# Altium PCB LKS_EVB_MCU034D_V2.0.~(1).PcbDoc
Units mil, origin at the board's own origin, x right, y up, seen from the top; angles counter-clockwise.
Board outline 2625 x 1560 mil, 2 copper layers (Top Layer, Bottom Layer); 35 components, 49 nets, 172 pads, 81 vias.
Unrouted connection lines stored in the file: 35.
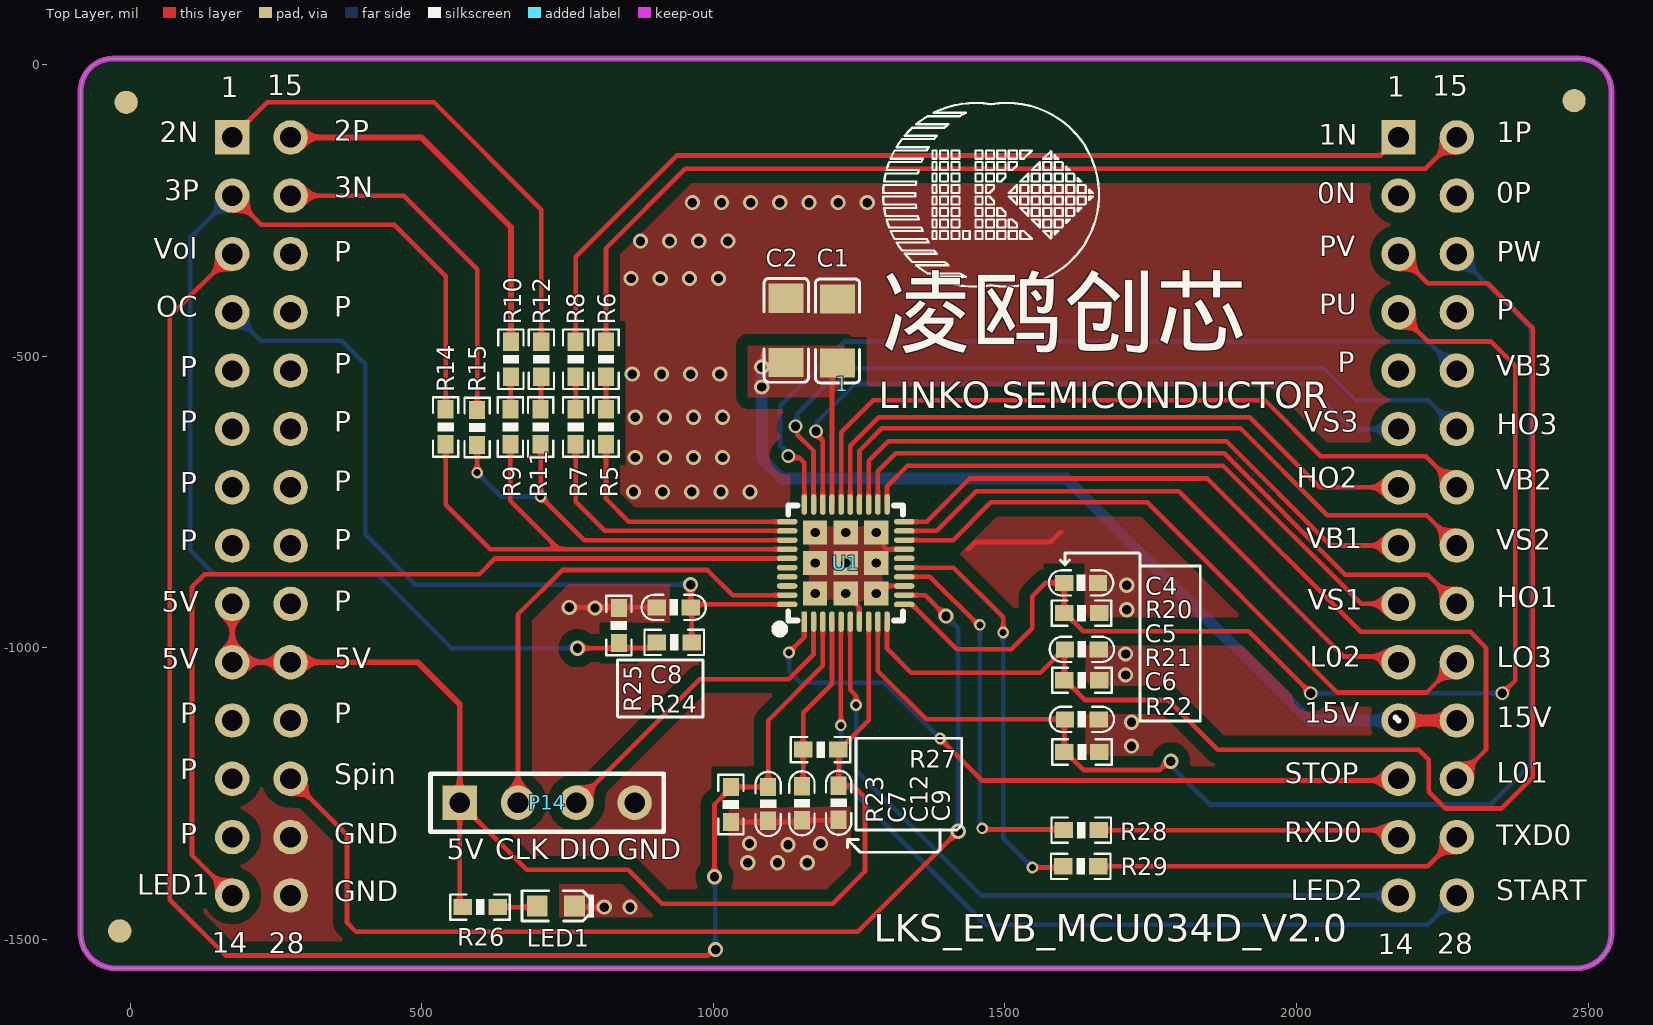
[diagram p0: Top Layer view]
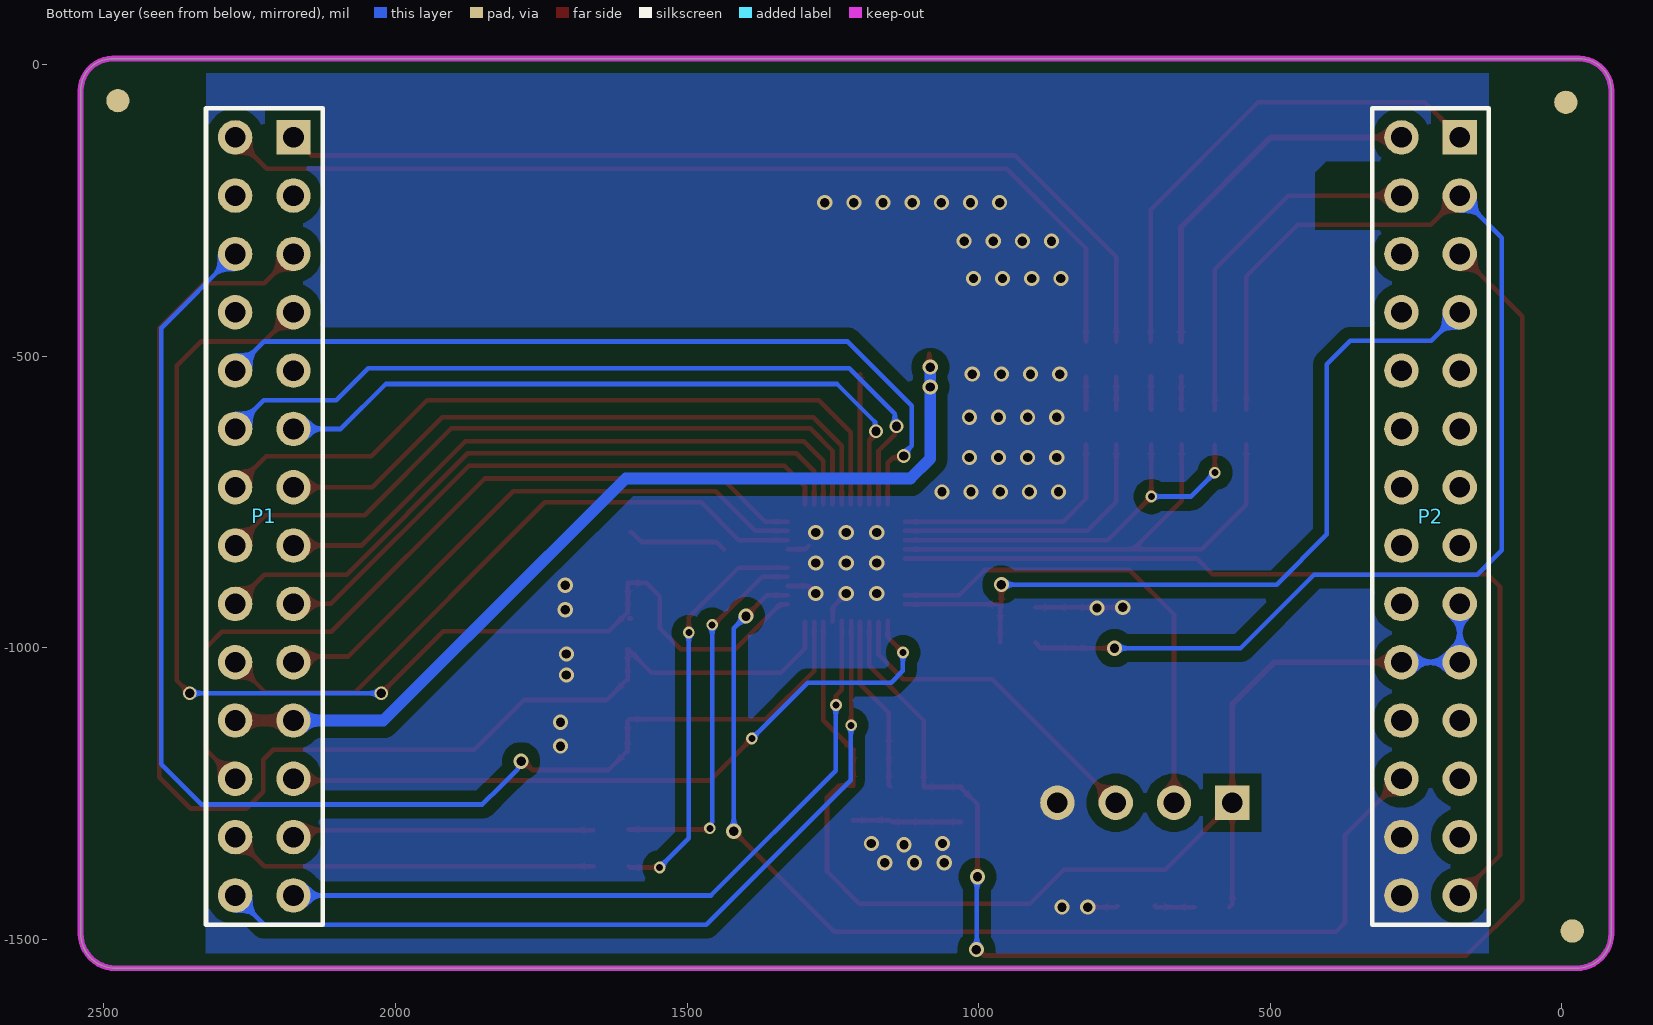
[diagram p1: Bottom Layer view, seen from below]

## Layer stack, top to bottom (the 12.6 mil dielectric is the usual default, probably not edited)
Top Solder: solder mask 0.4, Solder Resist, Dk 3.5
Top Layer: signal copper 1.4
Dielectric1: dielectric 12.6, FR-4, Dk 4.8
Bottom Layer: signal copper 1.4
Bottom Solder: solder mask 0.4, Solder Resist, Dk 3.5

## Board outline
-85,-1490 ccw(c-25,-1490) -25,-1550 2480,-1550 ccw(c2480,-1490) 2540,-1490 2540,-45 ccw(c2485,-45) 2485,10 -30,10 ccw(c-30,-45) -85,-45

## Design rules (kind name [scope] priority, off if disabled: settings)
Clearance Clearance_1 [InPolygon] p1: gap=20 ignorepadtopadclearanceinfootprint=FALSE except(0: Arc-Hole Track-Hole SMDPad-Hole THPad-Hole Via-Hole Fill-Hole Poly-Hole Region-Hole Text-Hole)
Clearance [All] p2: gap=5 ignorepadtopadclearanceinfootprint=FALSE
ComponentClearance [All] p1: gap=0 collisioncheckmode=3 verticalgap=0 showdistances=FALSE
FabricationTestpoint [(IsPad And (OnTopLayer Or OnBottomLayer))] p1: side=3 testpointundercomponent=TRUE minsize=40 maxsize=100 preferedsize=60 minholesize=0 maxholesize=40 preferedholesize=32 testpointgrid=1 allowsidetop=TRUE allowsidebottom=TRUE usegrid=TRUE gridtolerance=0.01
HoleSize [All] p1: absolutevalues=TRUE maxlimit=100 minlimit=0 maxpercent=80.000 minpercent=20.000
PolygonConnect [All] p1: connectstyle=Direct reliefconductorwidth=30 reliefentries=4 polygonreliefangle="90 Angle" airgapwidth=10
RoutingVias [All] p1: holewidth=12 width=20 viastyle="Through Hole" minholewidth=0 minwidth=10 maxholewidth=100 maxwidth=200
SilkToSolderMaskClearance SilkscreenOverComponentPads [IsPad] p1: minsilkscreentomaskgap=10 clearancetoexposedcopper=TRUE
SolderMaskExpansion [All] p1: expansion=4 istentingtop=FALSE
Width [All] p1: maxlimit=100 minlimit=2 preferedwidth=10
26 further rules are at their usual default settings.

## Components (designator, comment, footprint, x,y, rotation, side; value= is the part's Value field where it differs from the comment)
1 "LKS_sign" LKS_LOGO2 1221,-548 r0 top
C1 "22uF/25V" 1206C 1213,-457 r90 top
C2 "22uF/25V" 1206C 1125,-456 r90 top
C4 "1nF/16V" 0603C 1630.52,-889.02 r0 top
C5 "1nF/16V" 0603C 1632,-1003 r0 top
C6 "1nF/16V" 0603C 1632,-1123 r0 top
C7 "100nF/50V" 0603C 1094,-1268 r90 top
C8 "1nF/50V" 0603C 932,-931 r0 top
C9 "1uF/16V" 0603C 1215,-1266 r90 top
C12 "100nF/50V" 0603C 1152,-1267 r270 top
LED1 "LED" 0603D 730,-1443 r0 top
P1 "Header 14X2A" "HDR2 2X14 底层" 2175,-125 r270 bottom
P2 "Header 14X2A" "HDR2 2X14 底层" 175,-125 r270 bottom
P14 "Header 4" "HDR 1X4" 565,-1266 r0 top
R5 "20K" 0603R 815.95,-621.56 r270 top value=K
R6 "20K" 0603R 815.95,-505.56 r270 top value=K
R7 "20K" 0603R 763.95,-621.56 r270 top value=K
R8 "20K" 0603R 763.95,-505.56 r270 top value=K
R9 "20K" 0603R 651.95,-621.56 r270 top value=K
R10 "20K" 0603R 652.95,-505.56 r270 top value=K
R11 "20K" 0603R 703.95,-621.56 r270 top value=K
R12 "20K" 0603R 704.95,-505.56 r270 top value=K
R14 "1K" 0603R 540.95,-621.56 r270 top value=K
R15 "1K" 0603R 594.95,-622.56 r270 top value=K
R20 "1K" 0603R 1631.52,-941.02 r0 top value=K
R21 "1K" 0603R 1632.01,-1056 r0 top value=K
R22 "1K" 0603R 1632.05,-1179.01 r0 top value=K
R23 "1K" 0603R 1030,-1269 r90 top value=K
R24 "1K" 0603R 933,-991 r180 top value=K
R25 "10R" 0603R 838,-962 r90 top value=K
R26 "3.3K" 0603R 600,-1445 r180 top value=330
R27 "20K" 0603R 1184,-1175 r180 top value=K
R28 "10R" 0603R 1631,-1313 r180 top value=K
R29 "10R" 0603R 1630,-1375 r180 top value=K
U1 "LKS034DO" LINKO-084D 1156.13,-955.39 r90 top

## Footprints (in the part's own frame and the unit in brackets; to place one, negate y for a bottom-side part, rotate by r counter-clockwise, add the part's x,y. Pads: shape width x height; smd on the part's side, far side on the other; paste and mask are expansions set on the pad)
0603C [mm] "电容"
  rect 0.8x0.7 smd: 1(-0.737,0) 2(0.738,0)
  silkscreen extent -1.4,-0.55 1.4,0.55, body extent -0.8,-0.41 0.8,0.41, height 0.81
0603D [mm]
  rect 0.9x0.9 smd: 1(-0.813,0) 2(0.813,0)
  silkscreen extent -1.47,-0.66 1.65,0.66
0603R [mm] "电阻"
  rect 0.8x0.7 smd: 1(-0.762,0) 2(0.762,0)
  silkscreen extent -1.3,-0.55 1.3,0.55, body extent -0.8,-0.4 0.8,0.4, height 0.45
1206C [mil]
  rect 50x60 smd: 1(-55,0) 2(55,0)
  silkscreen extent -89,-38 89,38, body extent -61,-31 65,32, height 24
"HDR2 2X14 底层" [mm] "排针-双 2.54mm 底层"
  rect 1.5x1.5 hole 0.9: 1(0,0)
  round 1.5 hole 0.9: 2(2.54,0) 3(5.08,0) 4(7.62,0) 5(10.16,0) 6(12.7,0) 7(15.24,0) 8(17.78,0) 9(20.32,0) 10(22.86,0) 11(25.4,0) 12(27.94,0) 13(30.48,0) 14(33.02,0) 15(0,-2.54) 16(2.54,-2.54) 17(5.08,-2.54) 18(7.62,-2.54) 19(10.16,-2.54) 20(12.7,-2.54) 21(15.24,-2.54) 22(17.78,-2.54) 23(20.32,-2.54) 24(22.86,-2.54) 25(25.4,-2.54) 26(27.94,-2.54) 27(30.48,-2.54) 28(33.02,-2.54)
  silkscreen extent -1.27,-3.81 34.29,1.27, body extent -1.27,-6.35 34.29,-1.27, height 8.5
"HDR 1X4" [mm] "排针-单 2.54mm"
  rect 1.5x1.5 hole 0.9: 1(0,0)
  round 1.5 hole 0.9: 2(2.54,0) 3(5.08,0) 4(7.62,0)
  silkscreen extent -1.27,-1.27 8.89,1.27, body extent -1.27,-1.27 8.89,1.27, height 8.5
LINKO-084D [mm]
  rect 1.05x1.05 smd: 0(1.22,-3.13) 0(1.22,-0.47) 0(1.22,-1.8) 0(2.55,-1.8) 0(2.55,-0.47) 0(2.55,-3.13) 0(3.88,-3.13) 0(3.88,-1.8) 0(3.88,-0.47)
  rect 0.9x0.24 smd: 1(0,0)
  oval 0.9x0.24 smd: 2(0,-0.4) 3(0,-0.8) 4(0,-1.2) 5(0,-1.6) 6(0,-2) 7(0,-2.4) 8(0,-2.8) 9(0,-3.2) 10(0,-3.6) 21(5.1,-3.6) 22(5.1,-3.2) 23(5.1,-2.8) 24(5.1,-2.4) 25(5.1,-2) 26(5.1,-1.6) 27(5.1,-1.2) 28(5.1,-0.8) 29(5.1,-0.4) 30(5.1,0)
  oval 0.24x0.9 smd: 11(0.75,-4.35) 12(1.15,-4.35) 13(1.55,-4.35) 14(1.95,-4.35) 15(2.35,-4.35) 16(2.75,-4.35) 17(3.15,-4.35) 18(3.55,-4.35) 19(3.95,-4.35) 20(4.35,-4.35) 31(4.35,0.75) 32(3.95,0.75) 33(3.55,0.75) 34(3.15,0.75) 35(2.75,0.75) 36(2.35,0.75) 37(1.95,0.75) 38(1.55,0.75) 39(1.15,0.75) 40(0.75,0.75)
  silkscreen extent -0.44,-4.3 5.05,1.19
LKS_LOGO2 [mil] "标?"
  silkscreen extent 70,167 440,482

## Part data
C1 C2: library part Capacitor, "Capacitor --贴片电容"
C4 C5 C6: library part CAP, "Capacitor"
C7 C8 C9 C12: library part C, "Capacitor"
LED1: "LED_Light"
P1 P2: "Header, 14-Pin, Dual row"
P14: "Header, 4-Pin"
R5 R6 R7 R8 R9 R10 R11 R12 R14 R15 R20 R21 R22 R23 R24 R25 R26 R27 R28 R29: library part Res, "Resistor"
U1: library part LKS32MC034DF6Q8, "CHIP"

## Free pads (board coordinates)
  round 40 all layers, no hole: 5(-18,-1486) 5(-7,-65) 5(2476,-62)

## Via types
v1: diameter 26, hole 16, Top Layer to Bottom Layer, 66 vias
v2: diameter 20, hole 12, Top Layer to Bottom Layer, 10 vias
v3: diameter 23.62, hole 15.75, Top Layer to Bottom Layer, 5 vias

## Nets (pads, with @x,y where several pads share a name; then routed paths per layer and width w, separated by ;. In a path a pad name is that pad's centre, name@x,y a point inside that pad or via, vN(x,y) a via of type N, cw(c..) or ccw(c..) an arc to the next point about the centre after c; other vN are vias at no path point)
+5V: C9.2 P2.9 P2.10 P2.24 P14.1 R26.2 R27.1 U1.8 | length 2345.3
  Top Layer w8: R26.2 565,-1440 P14.1 680,-1381 854,-1381 912,-1439 1205,-1439 1260,-1384 1260,-1256.99 1239.96,-1236.95 C9.2 ; C9.2@1215,-1234.95 1215,-1176 R27.1 1215.97,-1175 1266.37,-1124.6 U1.8
  Top Layer w10: P2.9 P2.10 P2.24 493,-1025 565,-1097 P14.1
  Bottom Layer w8: P14.1 P14.1@567,-1268
  Bottom Layer w10: P2.9 P2.10 P2.24
+15V: C1.1 C2.1 P1.11 P1.25 U1.27 | length 1782
  Top Layer w8: v1(1083,-519) 1084.68,-517.32 1084.68,-495.97 ; U1.27 C1.1@1203.38,-531
  Top Layer w20: P1.11 P1.25
  Bottom Layer w20: v1(1083,-519) v1(1083,-553) 1083,-676 1117,-710 1605,-710 1737,-842 ; 1737.5,-841.5 2021,-1125 P1.11
GND: C1.2 C2.2 C4.2 C5.2 C6.2 C7.1 C8.1 C9.1 C12.2 LED1.2 P2.27 P2.28 P14.4 R20.2 R21.2 R22.2 R23.1 R25.2 U1.0 U1.7 U1.13 U1.17 | length 712.8
  Top Layer w8: v1(753,-931) C8.1 ; LED1.2 764,-1445 v1(813,-1445) ; R23.1 1149.05,-1299 C12.2 1213.95,-1296.05 C9.1 C9.1@1215,-1296.97 ; v1(1227,-907.36) 1250.34,-930.71 1250.34,-955.12 U1.7 ; v1(1279.36,-907.36) 1292.35,-894.37 U1.13 ; 1291.11,-825.28 1297.21,-831.38 U1.17 ; 1436.76,-831.38 1449.14,-819 1577.98,-819 1594.98,-802 1596.94,-802
  other v1: 857,-1445 1059,-1369 1110,-1369 1161,-1369 1128,-1338 1062,-1336 1184,-1336 1717,-1169 1717,-1128 1707,-1047 1707,-1011 1709,-935 797,-932 1174.64,-907.36 1709,-893 1174.64,-855 1227,-855 1279.36,-855 1174.64,-802.64 1227,-802.64 1279.36,-802.64 863,-733 913,-733 963,-733 1013,-733 1063,-733 866,-674 916,-674 966,-674 1016,-674 866,-605 916,-605 966,-605 1016,-605 861,-531 911,-531 961,-531 1011,-531 859,-367 909,-367 959,-367 1009,-367 875,-303 925,-303 975,-303 1025,-303 964,-237 1014,-237 1064,-237 1114,-237 1164,-237 1214,-237 1264,-237
GND0: P2.16 R15.1 | length 613.7
  Top Layer w8: P2.16 469,-225 594.95,-350.95 R15.1
HO1: P1.23 U1.22 | length 1169.3
  Top Layer w8: U1.22 1282.12,-697.88 1313,-667 1876,-667 2084,-875 2225,-875 P1.23
HO2: P1.7 U1.25 | length 1110.7
  Top Layer w8: U1.25 1234.87,-654.13 1284,-605 1920,-605 2040,-725 P1.7
HO3: P1.20 U1.29 | length 1376
  Top Layer w8: v3(1141,-620.47) 1143.99,-623.46 1143.99,-634.99 1171.88,-662.88 U1.29
  Bottom Layer w8: v3(1141,-620.47) 1143.99,-617.49 1143.99,-599.01 1222,-521 2047,-521 2102,-576 2226,-576 P1.20
LED1: P2.14 U1.35 | length 1598.4
  Top Layer w8: P2.14 106,-1356 106,-896 128,-874 599,-874 625.87,-847.13 U1.35
LED2: P1.14 U1.6 | length 1278.4
  Top Layer w8: U1.6@1234.51,-953.76 1234.51,-1072.24 1244.64,-1082.36 v2(1244.64,-1098.36)
  Bottom Layer w8: v2@1245,-1100 1245,-1211 1459,-1425 P1.14
LO1: P1.26 U1.20 | length 1394.1
  Top Layer w8: U1.20 1365.87,-784.13 1440,-710 1847,-710 2110,-973 2298,-973 2325,-1000 2325,-1175 P1.26
LO2: P1.10 U1.19 | length 997.1
  Top Layer w8: U1.19 1383.12,-799.88 1451,-732 1798,-732 2081.23,-1015.23 2165.23,-1015.23 P1.10
LO3: P1.24 U1.18 | length 1130.9
  Top Layer w8: U1.18 1411.37,-815.63 1476,-751 1744,-751 2070,-1077 2223,-1077 P1.24
NetLED1_1: LED1.1 R26.1 | length 70.2
  Top Layer w8: R26.1 696,-1445 LED1.1 LED1.1@697,-1442
NetR5_1: R5.1 R6.2 | length 56
  Top Layer w8: R5.1 R6.2
NetR7_1: R7.1 R8.2 | length 56
  Top Layer w8: R7.1 R8.2
NetR9_1: R9.1 R10.2 | length 56.4
  Top Layer w8: R9.1@652.45,-591.06 R10.2@652.45,-536.06
  Top Layer w9.45: R9.1 R9.1@652.45,-591.06 ; R10.2@652.45,-536.06 R10.2
NetR11_1: R11.1 R12.2 | length 56.4
  Top Layer w8: R11.1@704.45,-591.06 R12.2@704.45,-536.06
  Top Layer w9.45: R11.1 R11.1@704.45,-591.06 ; R12.2@704.45,-536.06 R12.2
NetR28_2: R28.2 U1.14 | length 655.3
  Top Layer w8: U1.14 1327.53,-878.48 1371.4,-878.48 1453.92,-961 v2(1457,-961) ; v2(1461,-1310) 1463,-1312 R28.2@1601,-1312
  Bottom Layer w8: v2(1457,-961) 1457,-1299.31 1458.7,-1301.02 1458.7,-1307.7 v2(1461,-1310)
NetR29_2: R29.2 U1.15 | length 708.4
  Top Layer w8: U1.15 1411.87,-862.87 1497,-948 v2(1497,-974) ; v2(1547,-1377) 1598,-1377 R29.2
  Bottom Layer w8: v2(1497,-974) 1497,-1327 v2(1547,-1377)
NRST: C12.1 R27.2 U1.4 | length 303.9
  Top Layer w8: C12.1 1154,-1236 R27.2 1154,-1112 1203.38,-1062.62 U1.4
OC: C8.2 P2.4 R24.1 U1.40 | length 1414.4
  Top Layer w8: v1(961,-892) 961.05,-892.05 C8.2 963,-932.95 R24.1 ; C8.2@962.52,-925.87 U1.40
  Bottom Layer w8: P2.4 224,-474 363,-474 403,-514 403,-806 489,-892 v1(961,-892)
OPA0_IN: R7.2 U1.32 | length 481.7
  Top Layer w8: R7.2 763.95,-749.95 813.88,-799.88 U1.32
OPA0_IP: R5.2 U1.31 | length 420.3
  Top Layer w8: R5.2 815.95,-744.95 855.13,-784.13 U1.31
OPA1_IN: R11.2 R15.2 U1.33 | length 716.4
  Top Layer w8: R15.2 v2(594.95,-699.95) v2@595,-700 ; R11.2 v2(703.95,-740.95) 778.63,-815.63 U1.33
  Bottom Layer w8: v2(594.95,-699.95) 635.95,-740.95 v2(703.95,-740.95)
OPA1_IP: R9.2 R14.2 U1.34 | length 934.9
  Top Layer w8: R14.2 540.95,-754.95 617.38,-831.38 735,-831.38 ; R9.2 651.95,-748.32 735,-831.38 ; U1.34 851.38,-831.38 735,-831.38
PGND: P2.2 R14.1 R24.2 R25.1 | length 2163.2
  Top Layer w8: P2.2 225,-275 453,-275 540.95,-362.95 R14.1 ; v1(767,-1001) 833.17,-1001 833.39,-1000.78 893.22,-1000.78 R24.2
  Bottom Layer w8: P2.2 103,-297 103,-833 145,-875 425,-875 551,-1001 v1(767,-1001)
PGND0: P1.2
PGND1: P1.1 R8.1 | length 1641.5
  Top Layer w8: R8.1 763.95,-330.05 938,-156 2144,-156 P1.1
PGND2: P2.1 R12.1 | length 857.6
  Top Layer w8: P2.1 235,-65 521,-65 704.95,-248.95 R12.1
PU: C4.1 P1.4 R20.1 U1.11 | length 2059
  Top Layer w8: U1.11 1340.39,-925.87 1417.52,-1003 1511,-1003 1547,-967 1547,-912 1569.98,-889.02 C4.1 R20.1 1603.49,-941.02 1634.47,-972 1918,-972 v3(2024.4,-1078.4) ; R20.1@1595.54,-950 R20.1@1600,-950 ; P1.4 2225,-475 2333,-475 2375,-517 2375,-1056.4 v3(2353,-1078.4)
  Bottom Layer w8: v3(2024.4,-1078.4) v3(2353,-1078.4)
PV: C5.1 P1.3 R21.1 U1.10 | length 2439.9
  Top Layer w8: U1.10 1297.87,-1001.87 1339,-1043 1561.03,-1043 1601.03,-1003 C5.1 1602.01,-1003.99 R21.1 1603.98,-1056 1637.97,-1090 1780,-1090 1865,-1175 2210,-1175 2227,-1192 2227,-1247 2256,-1276 2351,-1276 2405,-1222 2405,-452 2328,-375 2225,-375 P1.3
PW: C6.1 P1.17 R22.1 U1.9 | length 2303.2
  Top Layer w8: U1.9 1282.12,-1040.12 1365,-1123 1598.54,-1123 1602.05,-1126.52 R22.1 1604.02,-1179.01 1635.01,-1210 1764.69,-1210 1779.69,-1195 v1(1784.56,-1195)
  Bottom Layer w8: v1(1784.56,-1195) 1784.56,-1199.87 1790.46,-1205.77 1790.46,-1208.46 1819.5,-1237.5 1851,-1269 2333,-1269 2402,-1200 2402,-452 P1.17
RXD0: P1.13 R28.1 | length 519
  Top Layer w8: R28.1 2149.18,-1313 2161.18,-1325 P1.13
SPIN: P2.26 U1.12 | length 1877
  Top Layer w8: P2.26 371.93,-1321.93 371.93,-1471.93 387.25,-1487.25 1247.75,-1487.25 v1(1420,-1315) ; U1.12 1363.12,-910.12 v1(1399,-946)
  Bottom Layer w8: v1(1399,-946) 1420,-967 v1(1420,-1315)
START1: P1.28 U1.5 | length 1451.2
  Top Layer w8: v2@1218.64,-1133.36 v2(1218.76,-1133.24) U1.5@1218.76,-953.76
  Bottom Layer w8: v2@1219.13,-1134.87 1219.13,-1227.13 1467,-1475 2225,-1475 P1.28
STOP1: P1.12 U1.1 | length 1219.5
  Top Layer w8: v2(1129.64,-1008.36) 1155.77,-982.23 U1.1@1155.77,-953.76 ; v2(1389,-1156) 1461,-1228 2172,-1228 P1.12
  Bottom Layer w8: v2@1130,-1010 1130,-1040 1150,-1060 1293,-1060 v2(1389,-1156)
SWCLK: P14.2 U1.39 | length 833.9
  Top Layer w8: P14.2 665,-943 741,-867 990,-867 1033.12,-910.12 U1.39
SWDIO: P14.3 U1.2 | length 568.5
  Top Layer w8: P14.3 977,-1054 1129.59,-1054 1171.88,-1011.71 U1.2
TXD0: P1.27 R29.1 | length 635.7
  Top Layer w8: R29.1 2225,-1375 P1.27
UP-: P2.15 R10.1 | length 638.3
  Top Layer w10: P2.15 499,-125 652.95,-278.95 R10.1
VB1: P1.8 U1.23 | length 1071.7
  Top Layer w8: U1.23 1266.37,-679.63 1300,-646 1880,-646 2059,-825 P1.8
VB2: P1.21 U1.26 | length 1264.1
  Top Layer w8: U1.26 1219.13,-630.87 1274,-576 1946,-576 2042,-672 2222,-672 P1.21
VB3: P1.19 U1.30 | length 1435.7
  Top Layer w8: v3(1128.48,-671.48) 1131.47,-674.47 1147.44,-674.47 1156.13,-683.16 U1.30
  Bottom Layer w8: v3(1128.48,-671.48) 1128.48,-667.28 1115,-653.8 1115,-585 1225,-475 2225,-475 P1.19 P1.19@2265.47,-515.47
VOL_ADC: C7.2 P2.3 R23.2 U1.3 | length 2809.2
  Top Layer w8: P2.3 68,-432 68,-1432.31 163.69,-1528 990.31,-1528 1000.31,-1518 v1(1004,-1518) ; v1(1002,-1393) 1002,-1268.97 1030,-1240.97 R23.2 1030.05,-1238.95 C7.2 1094,-1125 1187.63,-1031.37 U1.3
  Bottom Layer w8: v1(1002,-1393) 1003,-1394 1003,-1517 v1(1004,-1518)
VP-: P1.15 R6.1 | length 1698.3
  Top Layer w8: R6.1 815.95,-315.05 952,-179 2221,-179 P1.15
VS1: P1.9 U1.21 | length 1021.3
  Top Layer w8: U1.21 1297.87,-723.13 1333,-688 1874,-688 2111,-925 P1.9
VS2: P1.22 U1.24 | length 1215.8
  Top Layer w8: U1.24 1250.62,-662.38 1289,-624 1904,-624 2053,-773 2223,-773 P1.22
VS3: P1.6 U1.28 | length 1203.1
  Top Layer w8: v3(1176,-629.11) 1176,-633.34 1187.63,-644.97 U1.28
  Bottom Layer w8: v3(1176,-629.11) 1177.73,-627.38 1177.73,-613.17 1242.91,-548 2017,-548 2094,-625 P1.6
WP-: P1.16
pads on no net: P1.5 P1.18 P2.5 P2.6 P2.7 P2.8 P2.11 P2.12 P2.13 P2.17 P2.18 P2.19 P2.20 P2.21 P2.22 P2.23 P2.25 U1.16 U1.36 U1.37 U1.38

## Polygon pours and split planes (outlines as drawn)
GND on Top Layer "GND_L01_P002" (solid, remove dead copper, pour order 2): 125,-1550 2325,-1550 2325,10 125,10
+15V on Top Layer "+15V_L01_P001" (solid, remove dead copper, pour order 1): 1059,-482 1059,-571 1202.38,-571 1225,-548.38 1225,-482
GND on Bottom Layer "GND_L02_P000" (solid, remove dead copper, pour order 0): 125,-1550 2325,-1550 2325,10 125,10

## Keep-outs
Keep-Out Layer:
  the board outline again, w10

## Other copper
Top Layer:
  pour cut-out: 218,-166 476,-166 625,-315 625,-616 556.96,-616 551,-610.04 551,-361 451,-261 447,-265 218,-265
Bottom Layer:
  pour cut-out: 218,-166 404,-166 424,-186 424,-284 228,-284 219,-275

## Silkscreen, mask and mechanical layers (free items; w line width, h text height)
Top Overlay:
  lines w5: 1249,-1329 1230,-1329 ; 1389,-1312 1389,-1346 1384,-1351 1252,-1351 1230,-1329 ; 1595,-850 1603,-858 ; 1230,-1329 1230,-1343 1230,-1329 ; 1603,-858 1611,-850 1603,-858 ; 1603,-858 1603,-838 1730,-838 1732,-840 1732,-860 ; 1732,-860 1835,-860 1835,-1126 1732,-1126 1732,-860 ; 836,-1118 836,-1021 982,-1021 982,-1119 837,-1119 836,-1118 ; 1245,-1313 1418,-1313 1426,-1305 1426,-1155.5 1245,-1155.5 1245,-1313
  lines w10: 2170,-1120 2175,-1125
  text "2P" at 350.06,-142.59 h60
  text "2N" at 50.91,-145 h60
  text "1P" at 2343.06,-145 h60
  text "1N" at 2038.03,-150 h60
  text "3N" at 350,-240 h60
  text "3P" at 58.01,-245 h60
  text "0P" at 2343,-249 h60
  text "0N" at 2035.31,-250 h60
  text "PV" at 2038.81,-341 h60
  text "Vol" at 40.03,-345 h60
  text "P" at 350.06,-349.98 h60
  text "PW" at 2343.06,-350 h60
  text "PU" at 2039.25,-440 h60
  text "OC" at 44.63,-445 h60
  text "P" at 350.06,-445 h60
  text "P" at 2343.06,-450 h60
  text "P" at 2071,-540 h60
  text "P" at 350.06,-542.69 h60
  text "VB3" at 2343,-546 h60
  text "P" at 85.93,-547.79 h60
  text "P" at 85.93,-640.99 h60
  text "P" at 350.06,-642.03 h60
  text "VS3" at 2012.73,-642 h60
  text "HO3" at 2343.06,-646 h60
  text "HO2" at 2000.52,-738 h60
  text "VB2" at 2343,-741 h60
  text "P" at 350.06,-743.49 h60
  text "P" at 85.93,-746.65 h60
  text "VB1" at 2016.72,-842 h60
  text "VS2" at 2343,-844 h60
  text "P" at 85.93,-845.18 h60
  text "P" at 350.06,-844.53 h60
  text "HO1" at 2343.06,-943 h60
  text "VS1" at 2019,-947 h60
  text "P" at 350.06,-950 h60
  text "5V" at 54.24,-950.94 h60
  text "L02" at 2022.72,-1045 h60
  text "LO3" at 2343.06,-1046 h60
  text "5V" at 350,-1047 h60
  text "5V" at 54.24,-1048.55 h60
  text "15V" at 2013.56,-1141 h60
  text "P" at 85.93,-1142 h60
  text "P" at 350.06,-1142 h60
  text "15V" at 2343.06,-1149 h60
  text "P" at 85.93,-1238 h60
  text "L01" at 2343.06,-1244 h60
  text "STOP" at 1980.15,-1245 h60
  text "Spin" at 350,-1246 h60
  text "RXD0" at 1978.7,-1346 h60
  text "P" at 85.93,-1348 h60
  text "GND" at 350.06,-1348 h60
  text "TXD0" at 2343,-1351 h60
  text "5V" at 543,-1375 h60
  text "CLK" at 626,-1375 h60
  text "DIO" at 735,-1375 h60
  text "GND" at 835,-1375 h60
  text "LED1" at 12,-1436 h60
  text "LED2" at 1989.8,-1445 h60
  text "START" at 2343,-1445 h60
  text "GND" at 350.06,-1447 h60
  text "LKS_EVB_MCU034D_V2.0" at 1275,-1520 h80
Top Solder:
  circle w78: c-18,-1486 r17
  circle w78: c-7,-65 r17
  circle w78: c2476,-62 r17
